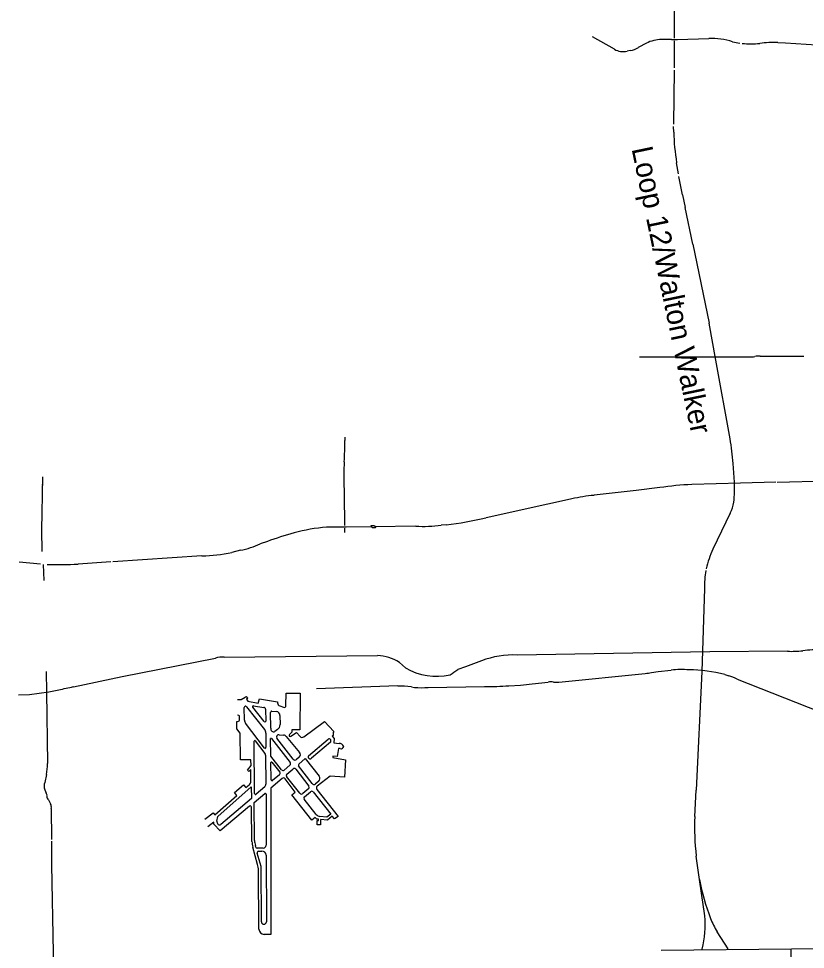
# Model space of a CAD drawing. Extents: x 105094 to 105814, y -291615 to -291123.
# Drawn here: x 105350 to 105395.2, y -291501.5 to -291448 of the extents above; entities that cross this region are included whole.
import ezdxf

# ---------------------------------------------------------------- set-up
doc = ezdxf.new("R2010")
doc.units = 0
doc.layers.add('G_MAP', color=7, linetype='Continuous')

msp = doc.modelspace()

# ---------------------------------------------------------------- linework, layer by layer
at = {"layer": 'G_MAP'}
for p, q in [((105387.653, -291446.773), (105387.662, -291449.127)), ((105384.222, -291449.768), (105382.956, -291449.051)), ((105387.84, -291449.202), (105389.658, -291449.153)), ((105386.056, -291449.423), (105385.595, -291449.663)), ((105387.504, -291449.202), (105386.934, -291449.205)), ((105387.504, -291449.202), (105387.84, -291449.202)), ((105387.659, -291449.282), (105387.649, -291450.839)), ((105393.614, -291449.384), (105394.063, -291449.399)), ((105394.063, -291449.399), (105396.482, -291449.56)), ((105385.134, -291449.844), (105384.945, -291449.883)), ((105387.662, -291450.965), (105387.62, -291454.075)), ((105387.628, -291454.526), (105387.62, -291454.201)), ((105387.904, -291456.93), (105387.798, -291456.297)), ((105388.143, -291458.134), (105387.927, -291457.078)), ((105388.143, -291458.134), (105388.295, -291458.874)), ((105388.731, -291460.967), (105388.295, -291458.874)), ((105388.731, -291460.967), (105389.668, -291465.523)), ((105390.052, -291467.652), (105389.668, -291465.523)), ((105385.665, -291467.449), (105392.139, -291467.461)), ((105390.87, -291472.169), (105390.052, -291467.652)), ((105390.633, -291467.458), (105392.139, -291467.461)), ((105392.606, -291467.413), (105395.109, -291467.422)), ((105368.712, -291472.078), (105368.712, -291472.257)), ((105391.121, -291474.653), (105391.047, -291473.588)), ((105351.295, -291474.814), (105351.373, -291474.821)), ((105351.318, -291476.419), (105351.349, -291474.356)), ((105368.666, -291474.337), (105368.692, -291476.901)), ((105391.476, -291474.724), (105388.679, -291474.802)), ((105393.495, -291474.669), (105391.476, -291474.724)), ((105397.134, -291474.582), (105393.582, -291474.682)), ((105385.473, -291475.134), (105383.05, -291475.418)), ((105386.832, -291474.976), (105385.473, -291475.134)), ((105380.657, -291475.864), (105380.386, -291475.922)), ((105381.772, -291475.622), (105380.657, -291475.864)), ((105380.386, -291475.922), (105376.837, -291476.704)), ((105390.88, -291476.446), (105389.887, -291478.518)), ((105368.692, -291476.901), (105368.692, -291477.162)), ((105366.273, -291477.467), (105365.805, -291477.582)), ((105368.599, -291477.24), (105368.141, -291477.24)), ((105368.796, -291477.24), (105368.599, -291477.24)), ((105368.692, -291477.304), (105368.696, -291477.563)), ((105370.268, -291477.227), (105368.796, -291477.24)), ((105372.797, -291477.194), (105370.449, -291477.224)), ((105374.544, -291477.107), (105374.263, -291477.133)), ((105362.715, -291478.577), (105362.214, -291478.699)), ((105364.265, -291478.073), (105363.861, -291478.208)), ((105360.506, -291478.903), (105355.377, -291479.245)), ((105351.231, -291479.374), (105350.003, -291479.268)), ((105351.383, -291479.394), (105351.407, -291480.317)), ((105355.264, -291479.248), (105353.386, -291479.369)), ((105389.403, -291480.779), (105389.248, -291485.556)), ((105389.707, -291484.409), (105378.623, -291484.603)), ((105394.176, -291484.383), (105389.707, -291484.409)), ((105361.791, -291484.726), (105370.598, -291484.632)), ((105376.582, -291484.932), (105375.655, -291485.271)), ((105351.545, -291485.54), (105351.577, -291486.734)), ((105371.857, -291485.026), (105372.209, -291485.333)), ((105375.655, -291485.271), (105375.213, -291485.439)), ((105388.612, -291485.436), (105388.935, -291485.449)), ((105381.025, -291486.156), (105385.99, -291485.659)), ((105389.248, -291485.556), (105388.919, -291492.363)), ((105390.568, -291485.726), (105390.792, -291485.801)), ((105391.273, -291485.988), (105395.983, -291487.853)), ((105367.084, -291486.518), (105371.77, -291486.35)), ((105372.545, -291486.428), (105372.723, -291486.466)), ((105373.514, -291486.47), (105376.75, -291486.415)), ((105378.155, -291486.366), (105378.815, -291486.326)), ((105379.497, -291486.265), (105380.414, -291486.158)), ((105351.577, -291486.734), (105351.624, -291490.848)), ((105362.947, -291488.338), (105362.937, -291487.618)), ((105363.066, -291487.572), (105364.099, -291488.882)), ((105364.09, -291488.432), (105363.422, -291487.608)), ((105363.473, -291487.521), (105364.062, -291487.614)), ((105364.984, -291487.531), (105365.191, -291487.607)), ((105362.619, -291488.072), (105362.541, -291488.052)), ((105362.673, -291488.298), (105362.673, -291488.141)), ((105364.168, -291487.723), (105364.171, -291488.401)), ((105364.459, -291488.803), (105364.456, -291487.903)), ((105364.526, -291487.825), (105364.779, -291487.85)), ((105364.992, -291488.082), (105364.995, -291488.597)), ((105364.103, -291489.953), (105363.01, -291488.522)), ((105364.175, -291489.1), (105364.175, -291489.902)), ((105364.523, -291488.977), (105364.52, -291488.974)), ((105364.847, -291488.888), (105364.695, -291488.995)), ((105364.95, -291489.181), (105365.201, -291489.208)), ((105365.354, -291489.29), (105366.12, -291490.205)), ((105363.532, -291492.561), (105363.516, -291489.546)), ((105363.569, -291489.532), (105364.129, -291490.254)), ((105364.459, -291490.413), (105364.455, -291489.392)), ((105364.5, -291489.4), (105365.578, -291490.775)), ((105365.757, -291490.59), (105364.804, -291489.389)), ((105366.623, -291490.39), (105367.756, -291489.436)), ((105367.892, -291489.612), (105366.797, -291490.539)), ((105364.164, -291490.355), (105364.181, -291492.031)), ((105368.648, -291489.842), (105368.657, -291489.86)), ((105365.076, -291491.2), (105364.459, -291490.413)), ((105364.478, -291491.774), (105364.472, -291490.777)), ((105364.522, -291490.764), (105364.982, -291491.346)), ((105366.103, -291490.466), (105365.951, -291490.605)), ((105366.073, -291490.871), (105366.448, -291490.558)), ((105366.448, -291490.558), (105367.243, -291491.56)), ((105365.561, -291490.934), (105365.23, -291491.215)), ((105365.389, -291491.454), (105365.734, -291491.162)), ((105365.898, -291491.163), (105366.66, -291492.148)), ((105366.834, -291491.992), (105366.061, -291490.971)), ((105351.565, -291491.467), (105351.47, -291491.927)), ((105365.118, -291491.697), (105364.472, -291492.253)), ((105364.964, -291491.485), (105364.562, -291491.816)), ((105366.139, -291492.549), (105365.376, -291491.584)), ((105367.209, -291491.866), (105367.025, -291492.015)), ((105351.467, -291492.347), (105351.554, -291492.544)), ((105364.121, -291492.176), (105363.625, -291492.604)), ((105366.649, -291492.267), (105366.308, -291492.565)), ((105366.392, -291492.761), (105366.748, -291492.461)), ((105366.894, -291492.476), (105367.908, -291493.755)), ((105388.841, -291493.891), (105388.919, -291492.363)), ((105351.69, -291492.928), (105351.799, -291493.164)), ((105363.345, -291492.848), (105361.588, -291494.346)), ((105363.513, -291493.074), (105364.115, -291492.566)), ((105364.197, -291492.604), (105364.197, -291495.537)), ((105367.078, -291493.768), (105366.38, -291492.885)), ((105351.835, -291493.422), (105351.858, -291495.208)), ((105363.381, -291495.316), (105363.351, -291493.341)), ((105363.529, -291495.267), (105363.513, -291493.074)), ((105361.44, -291494.34), (105361.42, -291494.32)), ((105363.706, -291496.649), (105363.429, -291495.649)), ((105363.599, -291495.643), (105363.577, -291495.547)), ((105364.029, -291495.706), (105363.683, -291495.709)), ((105363.903, -291496.765), (105363.684, -291495.998)), ((105363.766, -291495.886), (105363.952, -291495.88)), ((105364.2, -291496.105), (105364.21, -291499.942)), ((105389.109, -291497.511), (105388.922, -291496.164)), ((105363.923, -291499.941), (105363.903, -291496.765)), ((105363.785, -291500.374), (105363.751, -291496.968)), ((105390.753, -291501.5), (105390.127, -291500.518))]:
    msp.add_line(p, q, dxfattribs=at)
for points in [[(105351.328, -291478.651), (105351.302, -291477.398), (105351.315, -291476.419)], [(105353.117, -291486.421), (105355.914, -291485.83), (105361.284, -291484.784)], [(105386.354, -291485.607), (105386.739, -291485.546), (105387.484, -291485.468)], [(105349.965, -291486.896), (105350.582, -291486.863), (105351.693, -291486.715), (105352.274, -291486.595)], [(105362.557, -291487.157), (105362.757, -291487.157), (105362.984, -291487.019)], [(105363.101, -291487.036), (105363.138, -291487.077), (105363.073, -291487.141), (105363.151, -291487.248), (105363.742, -291487.374), (105363.81, -291487.119), (105364.85, -291487.293), (105364.854, -291487.354)], [(105365.337, -291487.512), (105365.35, -291486.802), (105366.151, -291486.799), (105366.138, -291488.895), (105365.68, -291488.898), (105365.676, -291489.043), (105365.536, -291489.164)], [(105363.325, -291491.838), (105363.325, -291491.178), (105363.206, -291491.298), (105363.119, -291491.223), (105363.329, -291490.955), (105363.325, -291490.635), (105362.725, -291490.626), (105362.699, -291489.089), (105362.505, -291488.843), (105362.502, -291488.427), (105362.553, -291488.424)], [(105366.354, -291489.307), (105367.549, -291488.427), (105368.089, -291489.001)], [(105365.621, -291489.272), (105365.935, -291489.05), (105366.143, -291489.285)], [(105368.044, -291489.131), (105368.044, -291489.224), (105367.995, -291489.26), (105368.108, -291489.399), (105368.095, -291489.651), (105368.402, -291489.679)], [(105367.896, -291489.465), (105367.901, -291489.476), (105367.892, -291489.612)], [(105368.46, -291489.983), (105368.347, -291489.983), (105368.279, -291490.439), (105368.027, -291490.409), (105368.021, -291490.503), (105368.764, -291490.619), (105368.699, -291491.617), (105367.869, -291491.572), (105367.133, -291492.145)], [(105367.11, -291492.337), (105368.344, -291493.888), (105368.121, -291494.026), (105367.995, -291493.871), (105367.721, -291494.094), (105367.327, -291494.056), (105367.327, -291494.366), (105367.139, -291494.359), (105367.13, -291494.12), (105367.21, -291494.12), (105367.214, -291494.039), (105367.101, -291494.033), (105367.023, -291493.942), (105366.816, -291494.094), (105365.673, -291492.635), (105365.86, -291492.48), (105365.289, -291491.716)], [(105360.671, -291494.043), (105361.142, -291493.681), (105361.239, -291493.791), (105362.505, -291492.686), (105362.376, -291492.515), (105362.899, -291492.056), (105363.022, -291492.228), (105363.217, -291492.067)], [(105361.367, -291494.148), (105361.42, -291493.881), (105363.329, -291492.176), (105363.345, -291492.848)], [(105364.472, -291492.253), (105364.472, -291500.663), (105364.075, -291500.663)], [(105363.248, -291493.296), (105361.559, -291494.714), (105361.184, -291494.327), (105361.187, -291494.207), (105360.848, -291494.475)], [(105367.908, -291493.755), (105367.695, -291493.93), (105367.287, -291493.884)], [(105351.861, -291495.302), (105351.861, -291496.675), (105351.948, -291501.725), (105351.945, -291505.087)], [(105411.499, -291501.48), (105410.689, -291501.429), (105402.938, -291501.448), (105398.63, -291501.464), (105394.402, -291501.522), (105386.9, -291501.593)], [(105394.519, -291517.95), (105394.464, -291510.177), (105394.377, -291501.487)]]:
    msp.add_lwpolyline(points, dxfattribs=at)
msp.add_lwpolyline([(105370.236, -291477.158), (105370.417, -291477.155), (105370.482, -291477.292), (105370.301, -291477.295)], close=True, dxfattribs=at)
for centre, radius, start, end in [((105389.774, -291453.434), 4.283, 73.188, 91.5525), ((105385.046, -291448.94), 0.908, 275.5393, 307.2332), ((105386.945, -291451.126), 1.921, 90.3359, 117.5644), ((105391.665, -291447.175), 2.256, 253.1952, 263.973), ((105392.083, -291445.29), 4.169, 262.9378, 276.8421), ((105393.384, -291455.89), 6.511, 87.9721, 97.0974), ((105384.737, -291448.858), 1.046, 240.4718, 281.4996), ((105400.277, -291454.206), 12.653, 181.4485, 189.5132), ((105392.141, -291467.101), 0.36, 269.7339, 294.4905), ((105392.59, -291470.197), 2.785, 89.6711, 96.1788), ((105378.088, -291474.486), 12.99, 3.9617, 10.2734), ((105356.88, -291472.6), 11.836, 355.6544, 1.6618), ((105383.104, -291474.196), 14.438, 177.2235, 180.5592), ((105389.111, -291489.243), 14.448, 91.711, 99.0743), ((105384.099, -291475.038), 7.032, 353.675, 3.1354), ((105383.924, -291485.032), 9.653, 95.1931, 102.8849), ((105388.525, -291475.318), 2.611, 334.4002, 349.0806), ((105372.696, -291459.897), 17.309, 276.1285, 283.8409), ((105368.141, -291485.04), 7.8, 90.0024, 103.8564), ((105373.183, -291468.874), 8.329, 267.3419, 277.4497), ((105370.408, -291494.689), 17.715, 105.0594, 110.2903), ((105361.668, -291473.348), 5.332, 281.3201, 294.2855), ((105394.63, -291480.789), 5.258, 154.4154, 167.3371), ((105360.301, -291469.907), 8.998, 271.305, 282.277), ((105352.292, -291462.313), 17.091, 267.6752, 273.6678), ((105394.55, -291480.656), 5.149, 169.7481, 181.3742), ((105394.423, -291479.258), 5.131, 267.2439, 276.9983), ((105395.983, -291493.041), 8.74, 88.8991, 96.1409), ((105361.678, -291485.975), 1.255, 84.8065, 108.2742), ((105370.501, -291487.153), 2.523, 57.4701, 87.7879), ((105378.42, -291489.832), 5.233, 87.7744, 110.5612), ((105374.011, -291482.284), 3.541, 239.4207, 282.3808), ((105371.41, -291480.371), 6.336, 302.0268, 306.8808), ((105388.081, -291491.135), 5.699, 85.7653, 96.0188), ((105388.461, -291493.712), 8.26, 75.2206, 89.7161), ((105385.9, -291483.714), 1.947, 272.6266, 283.4916), ((105390.173, -291488.103), 2.383, 62.5117, 74.9489), ((105348.957, -291468.436), 18.459, 280.3525, 283.0243), ((105371.959, -291490.728), 4.34, 82.2357, 92.5351), ((105373.146, -291479.684), 6.795, 266.4284, 273.1037), ((105376.731, -291465.467), 20.948, 270.0515, 273.8969), ((105378.068, -291474.069), 12.279, 273.4903, 276.6826), ((105380.581, -291487.498), 1.35, 84.1109, 97.1005), ((105380.878, -291484.645), 1.518, 264.0236, 275.5512), ((105363.032, -291487.098), 0.0927, 42.293, 121.4246), ((105363.01, -291487.617), 0.0721, 38.2862, 180.7167), ((105363.465, -291487.574), 0.0542, 81.0125, 218.9536), ((105364.041, -291487.741), 0.128, 7.9234, 80.6144), ((105365.054, -291487.343), 0.201, 183.2887, 249.7073), ((105365.228, -291487.505), 0.109, 249.717, 356.6201), ((105362.602, -291488.141), 0.0711, 359.9536, 76.0238), ((105364.52, -291487.89), 0.0657, 84.2595, 191.8177), ((105364.755, -291488.086), 0.237, 0.8093, 84.2253), ((105362.547, -291488.298), 0.126, 272.8172, 0.0084), ((105363.251, -291488.337), 0.304, 180.0964, 217.4054), ((105364.126, -291488.404), 0.0457, 219.0027, 3.5269), ((105364.646, -291488.604), 0.348, 305.1869, 1.0797), ((105363.823, -291489.1), 0.352, 359.9963, 38.282), ((105364.689, -291488.817), 0.23, 176.278, 222.7365), ((105364.619, -291488.887), 0.132, 223.0184, 305.1621), ((105364.934, -291489.325), 0.145, 83.7582, 206.398), ((105365.176, -291489.439), 0.232, 39.9094, 83.8073), ((105365.581, -291489.216), 0.069, 130.6908, 305.3038), ((105366.261, -291489.18), 0.157, 221.5544, 306.3387), ((105368.181, -291489.106), 0.139, 131.2989, 190.1209), ((105363.546, -291489.551), 0.0304, 38.2722, 169.8488), ((105364.464, -291489.475), 0.0829, 64.1146, 96.1086), ((105367.815, -291489.505), 0.0906, 26.6101, 130.0964), ((105368.373, -291489.988), 0.31, 27.9946, 84.7053), ((105364.138, -291489.927), 0.0439, 217.6606, 33.3707), ((105363.995, -291490.357), 0.169, 0.8, 37.824), ((105365.975, -291490.326), 0.189, 312.5832, 39.9362), ((105368.503, -291489.832), 0.157, 254.1944, 349.647), ((105348.721, -291490.883), 2.903, 348.3892, 0.697), ((105364.5, -291490.782), 0.0286, 38.8705, 169.3749), ((105365.487, -291490.846), 0.115, 310.2993, 38.0469), ((105365.861, -291490.507), 0.133, 218.4104, 312.571), ((105366.12, -291490.927), 0.0729, 129.8596, 217.0859), ((105366.72, -291490.453), 0.116, 147.059, 312.0887), ((105364.899, -291491.406), 0.102, 309.5113, 35.8907), ((105365.161, -291491.133), 0.108, 218.0877, 310.3201), ((105365.816, -291491.227), 0.104, 37.7724, 141.1403), ((105351.951, -291492.141), 0.526, 156.0497, 203.0686), ((105363.029, -291491.838), 0.296, 309.3627, 359.9971), ((105364.53, -291491.776), 0.0513, 177.67, 309.3591), ((105365.195, -291491.786), 0.117, 36.7805, 130.7448), ((105365.45, -291491.526), 0.0943, 130.206, 218.3221), ((105367.072, -291491.696), 0.219, 308.9116, 38.4518), ((105364.005, -291492.043), 0.176, 310.8627, 3.9771), ((105366.591, -291492.202), 0.0873, 311.0921, 37.8032), ((105366.814, -291492.54), 0.102, 38.3879, 130.0981), ((105366.941, -291491.911), 0.134, 217.1158, 308.9126), ((105367.217, -291492.252), 0.136, 127.8915, 218.4747), ((105351.383, -291492.674), 0.215, 352.5158, 37.2028), ((105351.84, -291492.734), 0.246, 172.6084, 232.3893), ((105363.588, -291492.562), 0.0561, 178.9361, 310.7113), ((105364.147, -291492.604), 0.0502, 0.0166, 130.2002), ((105366.231, -291492.476), 0.118, 218.3027, 311.1017), ((105366.449, -291492.829), 0.0891, 130.1569, 218.2673), ((105351.512, -291493.335), 0.335, 344.897, 30.7612), ((105363.288, -291493.344), 0.0625, 2.5784, 130.0834), ((105367.321, -291493.576), 0.31, 218.3216, 263.6081), ((105403.791, -291494.498), 14.962, 177.674, 186.3942), ((105361.555, -291494.185), 0.191, 168.8352, 225.0144), ((105361.517, -291494.262), 0.11, 224.969, 310.4545), ((105364.7, -291495.296), 1.319, 180.8444, 195.5034), ((105364.489, -291495.246), 0.96, 181.243, 198.3227), ((105363.682, -291495.624), 0.0853, 192.8983, 270.4153), ((105364.028, -291495.536), 0.17, 270.557, 0), ((105363.769, -291495.974), 0.0882, 91.8516, 195.8509), ((105363.959, -291496.122), 0.242, 4.0789, 91.758), ((105362.496, -291496.984), 1.255, 0.7234, 15.4825), ((105259.243, -291518.079), 131.485, 8.08035, 8.99965), ((105403.234, -291494.686), 14.405, 191.3214, 200.5487), ((105364.067, -291499.941), 0.144, 179.9467, 359.86), ((105383.617, -291500.067), 5.825, 345.701, 4.6279), ((105397.176, -291496.569), 8.083, 203.1191, 209.2443), ((105364.075, -291500.373), 0.29, 180.2084, 270.0056)]:
    msp.add_arc(centre, radius, start, end, dxfattribs=at)

# ---------------------------------------------------------------- texts
msp.add_text('Loop 12/Walton Walker', height=1.21107, rotation=281.819, dxfattribs=at).set_placement((105385.202, -291455.486))

doc.saveas('drawing.dxf')
